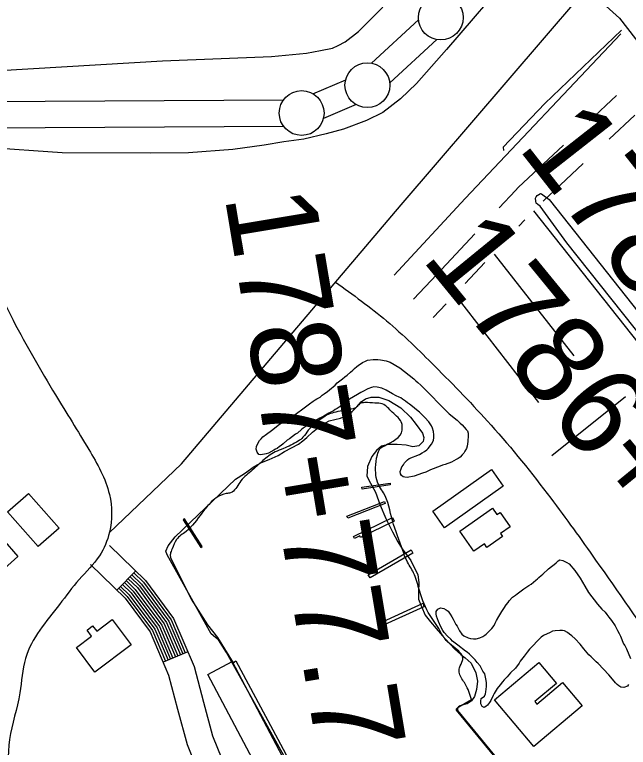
# Model space of a CAD drawing. Extents: x 3892998 to 3931244, y 278583 to 304547.
# Drawn here: x 3911353 to 3912038, y 284493 to 285311 of the extents above; entities that cross this region are included whole.
import ezdxf

# ---------------------------------------------------------------- set-up
doc = ezdxf.new("R2010")
doc.units = 0
for name, color, linetype in [('V-BLDG-OTLN', 7, 'Continuous'), ('V-CHAN-DOCK', 7, 'Continuous'), ('V-LEVE-TOET', 7, 'Continuous'), ('V-RIVR-EDGE', 7, 'Continuous'), ('V-ROAD-CNTR', 7, 'Continuous'), ('V-SITE-VEGE', 7, 'Continuous'), ('V-SURV-IDEN', 7, 'Continuous'), ('V-SURV-LINE', 7, 'Continuous'), ('V-TOPO-SHOR', 7, 'Continuous')]:
    doc.layers.add(name, color=color, linetype=linetype)

msp = doc.modelspace()

# ---------------------------------------------------------------- linework, layer by layer
at = {"layer": 'V-BLDG-OTLN'}
for points in [[(3911819.33, 284757.12), (3911884.75, 284803.38), (3911897.97, 284784.7), (3911832.55, 284738.43)], [(3911368.27, 284776.84), (3911402.29, 284738.07), (3911378.85, 284717.49), (3911344.82, 284756.26)], [(3911849.52, 284734.79), (3911885.95, 284760.28), (3911891, 284753.07), (3911894.59, 284755.58), (3911905.78, 284739.59), (3911894.89, 284731.97), (3911897.21, 284728.66), (3911879.85, 284716.51), (3911876.93, 284720.68), (3911865.11, 284712.5)], [(3911322.34, 284745.19), (3911356.36, 284706.43), (3911333.13, 284686.03), (3911299.1, 284724.8)], [(3911482.88, 284607.8), (3911442.35, 284577.28), (3911421.68, 284604.72), (3911438.65, 284617.49), (3911433.55, 284624.27), (3911439.79, 284628.97), (3911444.38, 284622.87), (3911461.7, 284635.92)], [(3911595.54, 284589.23), (3911675.9, 284437.11), (3911648.63, 284422.71), (3911568.28, 284574.83)], [(3911986.04, 284539.72), (3911931.99, 284494.24), (3911888.19, 284546.3), (3911937.78, 284588.04), (3911957.4, 284564.72), (3911933.18, 284544.34), (3911935.46, 284541.63), (3911964.14, 284565.75)]]:
    msp.add_lwpolyline(points, close=True, dxfattribs=at)
at = {"layer": 'V-CHAN-DOCK'}
for points in [[(3911771.8, 284786.23), (3911740.43, 284781.6), (3911740.13, 284783.59), (3911771.92, 284788.29), (3911771.8, 284786.23)], [(3911766.2, 284765.38), (3911724.51, 284749.03), (3911723.62, 284751.29), (3911765.51, 284767.71), (3911766.2, 284765.38)], [(3911540.88, 284747.48), (3911560.66, 284716.5), (3911562.06, 284717.4), (3911542.16, 284748.56), (3911540.88, 284747.48)], [(3911776.24, 284745.81), (3911738.68, 284727.6), (3911737.83, 284729.34), (3911731.99, 284726.51), (3911730.87, 284728.82), (3911774.49, 284749.97), (3911776.24, 284745.81)], [(3911797.21, 284710.21), (3911749.42, 284682.46), (3911747.4, 284685.93), (3911795.24, 284713.73), (3911797.21, 284710.21)], [(3911809.53, 284650.32), (3911760.95, 284628.07), (3911759.27, 284631.74), (3911808.63, 284654.35), (3911809.53, 284650.32)]]:
    msp.add_lwpolyline(points, dxfattribs=at)
at = {"layer": 'V-LEVE-TOET'}
for points in [[(3911335.97, 285248.84), (3911517.78, 285259.57), (3911639.22, 285264.6), (3911678.28, 285268.17), (3911693.9, 285271.02), (3911707.39, 285273.86), (3911713.78, 285276.71), (3911721.59, 285280.97), (3911736.5, 285292.34), (3911753.54, 285309.39), (3911850.79, 285408.86)], [(3911910.16, 285360.3), (3911834.71, 285272.2), (3911801.18, 285234.45), (3911783.22, 285217.06), (3911763.46, 285202.08), (3911745.49, 285193.09), (3911719.73, 285183.49), (3911700.56, 285178.09), (3911675.41, 285172.09), (3911653.24, 285169.08), (3911631.08, 285165.48), (3911596.33, 285160.67), (3911546.61, 285157.05), (3911504.68, 285156.43), (3911405.83, 285156.99), (3911320.16, 285162.94)]]:
    msp.add_lwpolyline(points, dxfattribs=at)
at = {"layer": 'V-RIVR-EDGE'}
for p, q in [((3911526.57, 284705.31), (3911549.76, 284658.63)), ((3911549.76, 284658.63), (3911568.14, 284629.93)), ((3911568.14, 284629.93), (3911579.28, 284615.82)), ((3911579.28, 284615.82), (3911596.69, 284587.61)), ((3911596.69, 284587.61), (3911599.61, 284590.03)), ((3911599.61, 284590.03), (3911646.5, 284502.5)), ((3911848.61, 284538.43), (3911862.72, 284546.65)), ((3911847.15, 284536.97), (3911848.61, 284538.43)), ((3911847.15, 284534.55), (3911847.15, 284536.97)), ((3911897.5, 284473.72), (3911847.15, 284534.55)), ((3911646.5, 284502.5), (3911689.52, 284421.3))]:
    msp.add_line(p, q, dxfattribs=at)
msp.add_spline([(3911862.72, 284546.65), (3911855.48, 284564.15), (3911849.19, 284575.82), (3911849.21, 284582.13), (3911852.63, 284590.38), (3911852.64, 284594.26), (3911848.28, 284600.59), (3911832.78, 284614.71), (3911826, 284625.9), (3911814.39, 284643.89), (3911803.78, 284670.63), (3911797.99, 284688.13), (3911790.26, 284701.74), (3911785.91, 284712.92), (3911774.34, 284746.46), (3911764.22, 284777.57), (3911759.86, 284784.38), (3911755.55, 284805.27), (3911757.52, 284819.83), (3911760.46, 284826.63), (3911765.32, 284830.01), (3911785.27, 284847.45), (3911785.28, 284850.36), (3911784.81, 284854.73), (3911774.15, 284867.38), (3911763.01, 284876.64), (3911754.75, 284877.63), (3911743.59, 284878.14), (3911737.75, 284876.7), (3911733.86, 284872.83), (3911730.46, 284871.38), (3911711.02, 284867.54), (3911703.25, 284865.13), (3911694.49, 284859.81), (3911687.19, 284854), (3911680.38, 284847.22), (3911674.53, 284839.46), (3911669.18, 284835.11), (3911652.65, 284826.89), (3911643.41, 284823.03), (3911629.79, 284813.35), (3911616.16, 284801.24), (3911603.99, 284789.13), (3911593.76, 284777.5), (3911588.9, 284776.54), (3911578.21, 284772.2), (3911570.91, 284765.9), (3911561.65, 284754.76), (3911544.12, 284734.4), (3911533.41, 284725.2), (3911528.53, 284715.02), (3911526.57, 284709.19), (3911526.57, 284705.31)], degree=3, dxfattribs=at)
at = {"layer": 'V-ROAD-CNTR'}
for p, q in [((3911994.38, 285192.77), (3912024.5, 285220.95)), ((3912016.32, 285172.21), (3912045, 285199.04)), ((3912070.73, 284917.06), (3911932.24, 285092.14)), ((3911977.21, 284930.23), (3911888.4, 285043.67)), ((3911937.62, 284878.16), (3911845.29, 284997.18)), ((3911952.38, 284819.04), (3912034.49, 284884.87)), ((3911487.84, 284690.21), (3911466.88, 284668.75)), ((3911545.99, 284600.11), (3911518.42, 284588.29))]:
    msp.add_line(p, q, dxfattribs=at)
for points in [[(3911458.39, 284732.66), (3911538.94, 284809.9), (3911784.15, 285098.85), (3912022.93, 285377.56)], [(3911990.76, 285340.68), (3912027.74, 285307.1), (3912060.95, 285264.29), (3912083.4, 285227.24), (3912099.11, 285189.11), (3912101.95, 285136.1), (3912117.8, 285084.07), (3912163.52, 285023.55), (3912208.03, 284965.73), (3912265.7, 284891.84), (3912322.26, 284818.03), (3912336.82, 284784.81), (3912328.35, 284763.72), (3912303.54, 284744.55), (3912274.58, 284728.67), (3912234.33, 284706.25), (3912218.45, 284711.89), (3912182.75, 284750.47)], [(3912029.27, 285289.72), (3911855.38, 285105.98), (3911776.1, 285020.58)], [(3911893.58, 285095.69), (3911911.48, 285114.8), (3911914.56, 285118.09), (3911965.17, 285165.44)], [(3911942.39, 285103.04), (3911987.11, 285144.88)], [(3911915.47, 285075.18), (3911921.93, 285082.08)], [(3911797.87, 284993.51), (3911823.73, 285021.12), (3911866.23, 285066.49)], [(3911855.35, 285011), (3911877.29, 285034.41)], [(3911819.76, 284973), (3911834.3, 284988.53)], [(3911458.54, 284718.83), (3911498.77, 284679.54), (3911530.04, 284637.32), (3911553.07, 284583.61), (3911563.48, 284543.77), (3911573.6, 284506.09), (3911593.64, 284456.67), (3911608.06, 284401.11), (3911594.44, 284356.72), (3911571.68, 284330.66), (3911539.71, 284295.39), (3911521.07, 284262.01)], [(3911437.58, 284697.37), (3911476.09, 284659.75), (3911503.85, 284622.27), (3911524.61, 284573.85), (3911534.48, 284536.08), (3911545.11, 284496.52), (3911554.64, 284473.02)], [(3911485.74, 284688.07), (3911496.5, 284677.56), (3911527.42, 284635.81), (3911543.23, 284598.93)], [(3911477.36, 284679.48), (3911487.43, 284669.65), (3911516.94, 284629.79), (3911532.2, 284594.2)], [(3911479.45, 284681.63), (3911489.7, 284671.62), (3911519.56, 284631.3), (3911534.96, 284595.38)], [(3911481.55, 284683.77), (3911491.96, 284673.6), (3911522.18, 284632.8), (3911537.72, 284596.57)], [(3911483.65, 284685.92), (3911494.23, 284675.58), (3911524.8, 284634.31), (3911540.48, 284597.75)], [(3911468.97, 284670.9), (3911478.35, 284661.73), (3911506.47, 284623.78), (3911521.18, 284589.47)], [(3911471.07, 284673.04), (3911480.62, 284663.71), (3911509.08, 284625.28), (3911523.93, 284590.65)], [(3911473.17, 284675.19), (3911482.89, 284665.69), (3911511.71, 284626.79), (3911526.69, 284591.84)], [(3911475.26, 284677.34), (3911485.16, 284667.67), (3911514.32, 284628.29), (3911529.45, 284593.02)]]:
    msp.add_lwpolyline(points, dxfattribs=at)
for points in [[(3911405.14, 285476.54), (3911368.03, 285435.22), (3911319.51, 285359.71), (3911288.83, 285256.28), (3911283.58, 285196.69), (3911289.75, 285128.71), (3911312.38, 285055.09), (3911351.14, 284970), (3911398.27, 284886.97), (3911435.54, 284825.79), (3911458.52, 284775.54), (3911458.57, 284733.36), (3911447.37, 284707.21), (3911424.83, 284680.71), (3911402.86, 284652.84), (3911364.86, 284592.7), (3911358.62, 284554.02), (3911347.16, 284502.19), (3911347.39, 284449.73), (3911373.97, 284365.08), (3911438.24, 284280.62), (3911451.25, 284265.01)], [(3911710.91, 285012.55), (3911767.75, 284969.4), (3911821.57, 284918.81), (3911884.37, 284853.05), (3911950.99, 284771.62), (3912001.08, 284702.39), (3912075, 284595.07), (3912141.79, 284493.5), (3912210.24, 284397.37), (3912244.8, 284346.66), (3912272.8, 284294.96), (3912279.9, 284279.29)]]:
    msp.add_spline(points, degree=3, dxfattribs=at)
at = {"layer": 'V-SITE-VEGE'}
for points in [[(3911698.27, 284888.05), (3911702.02, 284890.62), (3911704, 284892.4), (3911710.31, 284897.74), (3911712.68, 284900.11), (3911718.8, 284904.85), (3911721.17, 284906.82), (3911723.73, 284908.6), (3911727.68, 284911.96), (3911730.05, 284914.33), (3911731.83, 284916.31), (3911734.59, 284918.28), (3911736.17, 284919.66), (3911740.91, 284922.83), (3911744.27, 284924.41), (3911746.64, 284925.4), (3911752.76, 284926.39), (3911758.09, 284926.39), (3911760.85, 284926), (3911767.17, 284924.62), (3911771.71, 284923.43), (3911782.58, 284917.12), (3911798.38, 284904.69), (3911800.35, 284902.51), (3911802.53, 284900.74), (3911805.89, 284897.58), (3911837.7, 284865.8), (3911846.39, 284858.7), (3911848.17, 284856.92), (3911849.75, 284855.14), (3911852.12, 284853.17), (3911856.66, 284848.23), (3911858.04, 284846.46), (3911858.83, 284844.09), (3911859.03, 284841.32), (3911858.64, 284834.81), (3911857.66, 284829.48), (3911856.87, 284827.1), (3911855.09, 284823.95), (3911853.91, 284821.57), (3911852.33, 284819.8), (3911849.76, 284817.42), (3911847.59, 284815.84), (3911845.62, 284814.66), (3911840.09, 284811.7), (3911833.18, 284809.12), (3911830.22, 284808.33), (3911827.65, 284807.15), (3911816.99, 284802.99), (3911814.62, 284801.81), (3911811.66, 284800.62), (3911807.71, 284799.24)], [(3911807.71, 284799.24), (3911798.43, 284796.08), (3911790.93, 284794.49), (3911788.36, 284794.89), (3911786.39, 284795.48), (3911784.6, 284796.66), (3911783.42, 284798.83), (3911783.02, 284801.4), (3911784.01, 284804.36), (3911785, 284806.54), (3911786.77, 284808.51), (3911787.96, 284810.88), (3911789.73, 284812.86), (3911791.31, 284814.44), (3911793.09, 284815.82), (3911804.54, 284820.17), (3911807.7, 284822.15), (3911810.27, 284823.53), (3911812.63, 284825.51), (3911814.21, 284827.09), (3911817.96, 284831.83), (3911819.34, 284834.2), (3911820.13, 284836.17), (3911820.53, 284838.94), (3911820.72, 284842.29), (3911820.13, 284846.05), (3911818.94, 284849.6), (3911817.76, 284852.36), (3911816.57, 284854.34), (3911814.99, 284856.51), (3911810.65, 284861.44), (3911808.87, 284863.03), (3911804.52, 284867.56), (3911801.36, 284869.93), (3911798.99, 284871.91), (3911796.81, 284873.88), (3911793.46, 284876.44), (3911791.09, 284878.02), (3911788.91, 284879.8), (3911785.75, 284882.17), (3911783.78, 284883.35), (3911781.8, 284884.14), (3911778.64, 284885.72), (3911774.3, 284888.09), (3911767.38, 284892.03), (3911762.45, 284894.4), (3911757.12, 284895.39), (3911753.56, 284895.58), (3911750.99, 284894.99), (3911746.85, 284893.6), (3911741.32, 284890.64), (3911739.15, 284889.26), (3911735.4, 284887.28), (3911726.31, 284881.95), (3911723.95, 284880.17), (3911720.59, 284877.4), (3911715.85, 284873.84), (3911712.69, 284871.67), (3911710.52, 284870.48), (3911708.55, 284869.1), (3911703.22, 284866.33), (3911697.89, 284863.17), (3911693.15, 284860.8), (3911677.95, 284851.71), (3911674.79, 284849.54), (3911673.01, 284847.96), (3911668.27, 284844.2), (3911666.3, 284842.82), (3911659.59, 284837.68), (3911657.02, 284836.1), (3911652.48, 284832.15), (3911650.11, 284830.37), (3911648.33, 284829.18), (3911645.57, 284827.01), (3911643.79, 284826.03), (3911641.82, 284825.23), (3911636.1, 284821.87), (3911633.33, 284820.88), (3911627.6, 284819.69), (3911625.24, 284820.09), (3911623.26, 284822.66), (3911622.47, 284826.21), (3911622.67, 284829.17), (3911624.05, 284832.53), (3911626.02, 284835.89), (3911627.79, 284837.86), (3911629.77, 284839.84), (3911633.72, 284842.8), (3911639.24, 284847.15), (3911648.33, 284854.07), (3911653.85, 284857.43), (3911662.34, 284862.17), (3911667.47, 284865.92), (3911674.18, 284871.06), (3911681.89, 284876.79), (3911686.03, 284879.76), (3911688, 284881.14), (3911689.98, 284882.32), (3911693.53, 284884.1), (3911695.9, 284886.28), (3911698.27, 284888.05)], [(3911839.39, 284614.03), (3911835.64, 284617.58), (3911832.08, 284621.53), (3911830.69, 284623.7), (3911828.52, 284627.84), (3911825.75, 284633.96), (3911823.38, 284639.69), (3911822.98, 284642.26), (3911823.18, 284644.82), (3911824.96, 284647.59), (3911828.12, 284648.97), (3911831.67, 284648.18), (3911834.44, 284646.8), (3911836.41, 284645.23), (3911838.78, 284642.07), (3911840.76, 284639.11), (3911841.94, 284636.54), (3911843.33, 284634.17), (3911845.1, 284630.62), (3911846.49, 284628.44), (3911849.06, 284623.51), (3911851.83, 284619.76), (3911854.19, 284617.78), (3911858.94, 284615.42), (3911861.31, 284615.02), (3911864.66, 284614.63), (3911867.62, 284614.63), (3911871.77, 284615.42), (3911875.13, 284617), (3911877.3, 284618.39), (3911879.08, 284619.77), (3911885.39, 284626.09), (3911887.76, 284629.45), (3911889.14, 284632.02), (3911890.32, 284634.78), (3911893.09, 284639.33), (3911896.25, 284645.05), (3911898.61, 284648.41), (3911901.38, 284652.36), (3911903.55, 284654.93), (3911904.73, 284656.71), (3911908.48, 284660.86), (3911911.64, 284663.03), (3911913.42, 284664.61), (3911921.12, 284670.34), (3911923.29, 284671.72), (3911926.64, 284674.1), (3911929.01, 284675.48), (3911934.34, 284679.83), (3911936.12, 284681.41), (3911937.7, 284682.99), (3911940.26, 284685.16), (3911942.24, 284686.54), (3911948.55, 284692.67), (3911951.91, 284695.23), (3911954.87, 284697.61), (3911957.04, 284699.39), (3911959.21, 284701.36), (3911960.99, 284702.55), (3911964.54, 284701.76), (3911969.09, 284699.59), (3911971.46, 284698.01), (3911977.78, 284690.9), (3911983.91, 284682.02), (3911988.85, 284673.14), (3911993.19, 284666.03), (3912003.27, 284653.2), (3912008.01, 284647.67), (3912011.57, 284644.12), (3912013.74, 284641.55), (3912015.72, 284638.79), (3912018.88, 284634.84), (3912022.83, 284628.92), (3912025.6, 284623.59), (3912027.38, 284620.43), (3912028.96, 284617.27), (3912032.32, 284608.98), (3912033.7, 284607.2), (3912035.68, 284603.45), (3912040.03, 284592.59)], [(3911993.62, 284596.72), (3911988.09, 284603.23), (3911983.94, 284608.56), (3911978.41, 284614.48), (3911974.65, 284617.84), (3911972.08, 284619.81), (3911969.52, 284621.59), (3911966.36, 284623.36), (3911963.99, 284623.76), (3911961.22, 284623.96), (3911956.09, 284623.55), (3911952.93, 284622.96), (3911950.36, 284621.58), (3911943.06, 284618.02), (3911940.49, 284616.24), (3911937.53, 284613.67), (3911935.95, 284611.7), (3911931.41, 284606.95), (3911927.46, 284603.01), (3911924.5, 284599.45), (3911921.35, 284595.1), (3911916.8, 284589.57), (3911915.62, 284587.4), (3911911.48, 284581.87), (3911906.15, 284576.34), (3911902.2, 284571.99), (3911899.04, 284568.83), (3911897.07, 284566.66), (3911894.7, 284563.3), (3911891.35, 284559.15), (3911887.99, 284553.42), (3911886.81, 284551.25), (3911884.05, 284545.52), (3911882.66, 284543.35), (3911880.3, 284540.59), (3911878.72, 284539), (3911876.74, 284538.01), (3911874.57, 284538.8), (3911872.99, 284541.77), (3911872.99, 284544.92), (3911873.18, 284547.69), (3911877.13, 284550.46), (3911878.12, 284553.02), (3911878.71, 284555.39), (3911879.3, 284561.32), (3911879.3, 284565.27), (3911879.1, 284568.03), (3911877.32, 284575.54), (3911875.34, 284578.49), (3911872.38, 284584.22), (3911868.82, 284588.17), (3911866.65, 284590.93), (3911863.09, 284594.88), (3911860.32, 284597.45), (3911857.56, 284599.42), (3911855.98, 284600.8), (3911847.29, 284607.32), (3911841.36, 284611.85), (3911839.39, 284614.03)], [(3912037.87, 284563.56), (3912036.49, 284561.78), (3912032.73, 284560), (3912029.38, 284560.4), (3912027.01, 284561.98), (3912025.23, 284563.55), (3912023.25, 284565.53), (3912017.92, 284571.65), (3912015.94, 284574.41), (3912010.02, 284580.73), (3912004.09, 284586.85), (3912001.72, 284588.82), (3911999.55, 284591.19), (3911995.99, 284594.35), (3911993.62, 284596.72)]]:
    msp.add_lwpolyline(points, dxfattribs=at)
at = {"layer": 'V-SURV-LINE'}
for points in [[(3911750.92, 285256.99), (3911803.39, 285305.43)], [(3911823.73, 285283.38), (3911771.26, 285234.94)], [(3911685.6, 285222.96), (3911722.16, 285238.43)], [(3911319.83, 285214.31), (3911652.97, 285216.24)], [(3911733.83, 285210.8), (3911697.28, 285195.32)], [(3911653.15, 285186.24), (3911320.01, 285184.31)]]:
    msp.add_lwpolyline(points, dxfattribs=at)
for centre in [(3911828.25, 285307.96), (3911746.4, 285232.4), (3911673.03, 285201.35)]:
    msp.add_circle(centre, 25, dxfattribs=at)
at = {"layer": 'V-TOPO-SHOR'}
msp.add_line((3911968.78, 285056.65), (3911939.34, 285097.32), dxfattribs=at)
for points in [[(3912029.89, 285294.03), (3911944.23, 285212.05), (3911897.85, 285163.25), (3911898.44, 285159.5)], [(3911939.34, 285097.32), (3911936.58, 285099.09), (3911934.8, 285100.87), (3911934.21, 285103.04), (3911934.01, 285106.2), (3911934.8, 285107.98), (3911935.79, 285109.16), (3911937.56, 285110.35), (3911939.53, 285111.53), (3911940.52, 285111.34), (3911949.41, 285105.02), (3912106.09, 284906.44), (3912095.43, 284897.94), (3912094.84, 284898.34), (3911968.78, 285056.65)], [(3911686.39, 284424.65), (3911589.34, 284599.28), (3911580.08, 284613.44), (3911576.94, 284615.99), (3911572.21, 284620.12), (3911522.8, 284708.23), (3911521.42, 284712.16), (3911523.98, 284718.26), (3911532.04, 284728.29), (3911599.28, 284792.65), (3911609.31, 284798.95), (3911620.13, 284806.82), (3911628.19, 284811.15), (3911636.84, 284814.7), (3911646.68, 284819.22), (3911653.95, 284823.55), (3911661.82, 284827.69), (3911669.49, 284831.82), (3911674.41, 284835.56), (3911678.93, 284839.3), (3911685.22, 284845.01), (3911690.73, 284849.73), (3911697.61, 284854.46), (3911703.9, 284857.8), (3911710, 284859.38), (3911716.29, 284860.96), (3911722.59, 284863.52), (3911729.47, 284868.04), (3911734.58, 284873.55), (3911739.5, 284879.06), (3911744.22, 284882.41), (3911750.71, 284884.38), (3911759.17, 284884.19), (3911770.18, 284880.65), (3911783.76, 284872.4), (3911794.39, 284861.78), (3911800.68, 284853.72), (3911807.97, 284843.88), (3911809.35, 284839.16), (3911808.56, 284834.84), (3911803.65, 284829.92), (3911796.96, 284828.73), (3911789.68, 284830.5), (3911779.45, 284831.28), (3911769.81, 284831.47), (3911762.14, 284829.5), (3911756.64, 284824.59), (3911751.52, 284818.09), (3911746.61, 284806.68), (3911745.83, 284795.86), (3911749.96, 284788.19), (3911755.48, 284778.16), (3911760.6, 284763.61), (3911767.1, 284748.66), (3911774.58, 284733.91), (3911780.48, 284722.9), (3911785.21, 284715.03), (3911789.54, 284708.93), (3911794.85, 284701.85), (3911802.53, 284685.92), (3911803.71, 284677.47), (3911803.32, 284666.84), (3911803.52, 284658.78), (3911806.68, 284650.72), (3911811.01, 284640.88), (3911816.91, 284633.41), (3911823.01, 284626.13), (3911830.29, 284617.68), (3911838.36, 284609.03), (3911844.07, 284602.93), (3911850.76, 284596.84), (3911855.48, 284593.3), (3911862.18, 284587.2), (3911867.29, 284576.39)], [(3911867.29, 284576.39), (3911869.27, 284567.34), (3911868.29, 284558.09), (3911865.93, 284550.23), (3911862.39, 284545.11), (3911857.87, 284541.96), (3911853.34, 284540.97), (3911850, 284539.79), (3911848.03, 284538.41), (3911845.48, 284536.05), (3911845.48, 284534.87), (3911907.48, 284459.36), (3911937.59, 284419.84), (3911945.66, 284405.68), (3912026.16, 284297.13), (3912046.27, 284271.1)]]:
    msp.add_lwpolyline(points, dxfattribs=at)

# ---------------------------------------------------------------- texts
at = {"layer": 'V-SURV-IDEN'}
for s, rotation, p in [('1785+86.6', 308.12685, (3911913.13, 285163.19)), ('1787+77.7', 279.47505, (3911586.89, 285108.63)), ('1786+98.0', 309.27521, (3911805.43, 285039.07))]:
    msp.add_text(s, height=100, rotation=rotation, dxfattribs=at).set_placement(p)

doc.saveas('drawing.dxf')
